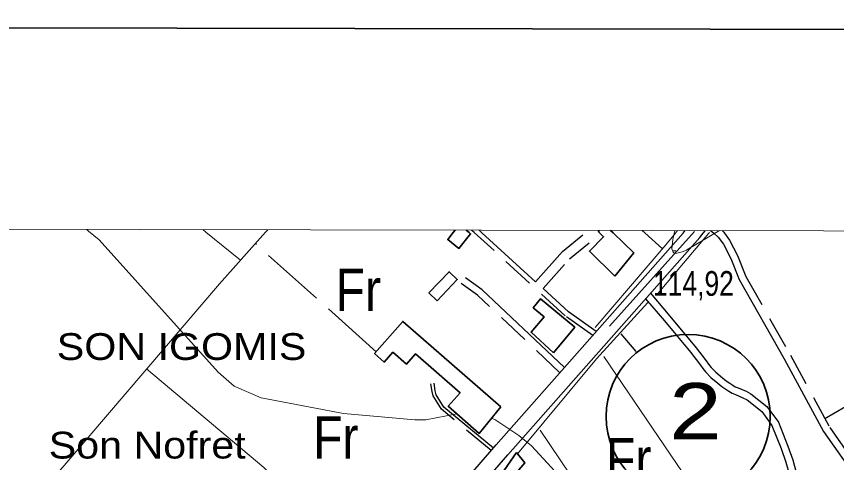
# Model space of a CAD drawing. Extents: x 483847 to 488453, y 4383581 to 4386795.
# Drawn here: x 486183.5 to 486474.2, y 4386361.3 to 4386519.6 of the extents above; entities that cross this region are included whole.
import ezdxf
from ezdxf.enums import TextEntityAlignment as Align

# ---------------------------------------------------------------- set-up
doc = ezdxf.new("R2010")
doc.units = 0
doc.header["$LTSCALE"] = 3.8
doc.linetypes.add('LONG_DASHED', pattern=[7.5, 6, -1.5])
doc.linetypes.add('MEDIUM_DASHED', pattern=[4.5, 3, -1.5])
for name, color, linetype, lineweight in [('1', 7, 'Continuous', 13), ('13', 7, 'Continuous', 25), ('25', 7, 'LONG_DASHED', 25), ('36', 7, 'Continuous', 25), ('38', 7, 'Continuous', 25), ('47', 7, 'Continuous', 35), ('51', 7, 'Continuous', 13), ('6', 7, 'Continuous', 35), ('7', 7, 'Continuous', 13), ('9', 7, 'Continuous', 13)]:
    doc.layers.add(name, color=color, linetype=linetype, lineweight=lineweight)
doc.layers.add('31', color=7, linetype='Continuous')
doc.layers.add('5', color=7, linetype='Continuous')

msp = doc.modelspace()

# ---------------------------------------------------------------- linework, layer by layer
at = {"layer": '1', "lineweight": 35}
msp.add_lwpolyline([(484035.03, 4386519.58), (487752.53, 4386512.52), (487747.86, 4384057.52), (484030.36, 4384064.59)], close=True, dxfattribs=at)
at = {"layer": '1'}
msp.add_lwpolyline([(484105.5, 4386448.1), (487681.9, 4386441.2), (487678, 4384129), (484100.5, 4384135.8)], close=True, dxfattribs=at)
at = {"layer": '25'}
msp.add_line((486311.07, 4386400.66), (486268.2, 4386438.96), dxfattribs=at)
msp.add_lwpolyline([(486470.05, 4386377.03), (486540.85, 4386417.71), (486530.1, 4386442.53)], dxfattribs=at)
at = {"layer": '36'}
for p, q in [((486419.82, 4386442.75), (486420.6, 4386443.63)), ((486426.98, 4386442.73), (486427.72, 4386443.62))]:
    msp.add_line(p, q, dxfattribs=at)
for points in [[(486304.43, 4386310.75), (486353.58, 4386367.64), (486419.82, 4386442.75)], [(486308, 4386306.63), (486357.67, 4386364.07), (486425.71, 4386441.21), (486426.98, 4386442.73)]]:
    msp.add_lwpolyline(points, dxfattribs=at)
at = {"layer": '38'}
for p, q in [((486348.51, 4386442.88), (486347.53, 4386443.77)), ((486367.53, 4386425.5), (486348.51, 4386442.88))]:
    msp.add_line(p, q, dxfattribs=at)
at = {"layer": '38', "linetype": 'MEDIUM_DASHED'}
for points in [[(486345.81, 4386442.89), (486344.99, 4386443.64), (486344.83, 4386443.78)], [(486387.8, 4386406.43), (486378.03, 4386413.43), (486345.81, 4386442.89)], [(486433.64, 4386443.61), (486434.21, 4386443.11), (486434.49, 4386442.72)], [(486434.49, 4386442.72), (486436.31, 4386440.2), (486439.11, 4386434.8), (486442.06, 4386427.36), (486457.9, 4386399.46), (486471.82, 4386373.74), (486486.78, 4386352.48), (486491.1, 4386348.94), (486494.66, 4386343.57), (486495.55, 4386341.07), (486495.52, 4386339.13)], [(486370.19, 4386423.06), (486379.57, 4386433.55), (486386.52, 4386439.29)], [(486376.16, 4386393.24), (486346.95, 4386420.72), (486341.2, 4386424.84)], [(486351.82, 4386365.61), (486334.16, 4386380.29), (486331.18, 4386384.98), (486330.82, 4386386.61), (486330.4, 4386389.32)]]:
    msp.add_lwpolyline(points, dxfattribs=at)
at = {"layer": '38'}
for points in [[(486429.54, 4386443.62), (486430.55, 4386442.86), (486430.71, 4386442.72)], [(486430.71, 4386442.72), (486432.29, 4386441.35), (486434.1, 4386438.84), (486436.75, 4386433.73), (486439.72, 4386426.24), (486455.63, 4386398.2), (486469.61, 4386372.37), (486484.87, 4386350.7), (486489.16, 4386347.19), (486492.33, 4386342.4), (486492.95, 4386340.64), (486492.93, 4386339.16)], [(486367.53, 4386425.5), (486377.07, 4386436.15), (486384.23, 4386442.07)], [(486377.83, 4386395.13), (486348.56, 4386422.67), (486342.67, 4386426.89)], [(486389, 4386407.79), (486379.18, 4386414.84), (486370.19, 4386423.06)], [(486408.24, 4386421.4), (486415.14, 4386413.31), (486424.51, 4386402.05), (486427.6, 4386397.88), (486429.22, 4386395.84), (486429.81, 4386395.09), (486431.43, 4386393.44), (486433.78, 4386391.45), (486435.03, 4386390.39), (486436.36, 4386389.56), (486437.4, 4386388.79), (486438.32, 4386388.27), (486439.36, 4386387.89), (486442.14, 4386386.64), (486443.88, 4386385.77), (486449.56, 4386381.3), (486453.58, 4386375.72), (486456.99, 4386367.23), (486458.73, 4386362.31), (486459.94, 4386357.8)], [(486406.53, 4386419.46), (486413.19, 4386411.65), (486422.5, 4386400.47), (486425.58, 4386396.33), (486427.21, 4386394.26), (486427.88, 4386393.4), (486429.68, 4386391.56), (486432.13, 4386389.5), (486433.51, 4386388.32), (486434.92, 4386387.44), (486436, 4386386.64), (486437.25, 4386385.94), (486438.39, 4386385.51), (486441.04, 4386384.32), (486442.5, 4386383.6), (486447.7, 4386379.52), (486451.31, 4386374.48), (486454.6, 4386366.32), (486456.28, 4386361.56), (486457.49, 4386357.04)], [(486352.57, 4386366.47), (486335.03, 4386381.06), (486332.25, 4386385.42), (486331.95, 4386386.82), (486331.54, 4386389.5)]]:
    msp.add_lwpolyline(points, dxfattribs=at)
at = {"layer": '47'}
for p, q in [((486339.06, 4386443.79), (486338.35, 4386442.9)), ((486344, 4386442.89), (486342.88, 4386443.78)), ((486394.13, 4386443.68), (486395.05, 4386442.79))]:
    msp.add_line(p, q, dxfattribs=at)
for points in [[(486338.35, 4386442.9), (486336.4, 4386440.44), (486340.33, 4386437.32), (486344.46, 4386442.53), (486344, 4386442.89)], [(486395.57, 4386427.52), (486386.62, 4386436.28), (486391.64, 4386441.42), (486390.22, 4386442.8)], [(486390.22, 4386442.8), (486389.73, 4386443.28), (486390.13, 4386443.69)], [(486395.05, 4386442.79), (486402.37, 4386435.71), (486395.57, 4386427.52)]]:
    msp.add_lwpolyline(points, dxfattribs=at)
for points in [[(486332.64, 4386418.75), (486339.77, 4386426.25), (486336.84, 4386429.04), (486329.71, 4386421.54)], [(486373.87, 4386400.22), (486381.43, 4386409.34), (486369.27, 4386419.41), (486366.68, 4386416.28), (486370.52, 4386413.09), (486365.92, 4386407.55)], [(486355.21, 4386381.13), (486320.45, 4386411.42), (486310.48, 4386399.99), (486313.89, 4386397.01), (486316.94, 4386400.51), (486321.78, 4386396.28), (486324.93, 4386399.9), (486340.75, 4386386.13), (486336.55, 4386381.32), (486347.55, 4386371.69)], [(486360.76, 4386364.92), (486354.09, 4386355.41), (486356.68, 4386352.97), (486363.71, 4386361.27)]]:
    msp.add_lwpolyline(points, close=True, dxfattribs=at)
at = {"layer": '51'}
for p, q in [((486249.54, 4386443.96), (486250.64, 4386443.07)), ((486250.64, 4386443.07), (486262.95, 4386433.11)), ((486271.85, 4386443.03), (486272.65, 4386443.92)), ((486405.29, 4386443.66), (486406.28, 4386442.77)), ((486406.28, 4386442.77), (486412.5, 4386437.16)), ((486428.99, 4386442.73), (486411.01, 4386421.45)), ((486417.15, 4386442.75), (486417.88, 4386443.64)), ((486429.18, 4386442.95), (486428.99, 4386442.73)), ((486456.75, 4386303.26), (486391.78, 4386398.99))]:
    msp.add_line(p, q, dxfattribs=at)
for points in [[(486195.55, 4386354.65), (486255.51, 4386424.8), (486271.85, 4386443.03)], [(486388.63, 4386409.24), (486413.66, 4386438.52), (486417.15, 4386442.75)], [(486407.29, 4386418.13), (486389.07, 4386398.2), (486361.13, 4386364.48)], [(486229.66, 4386394.55), (486271.24, 4386359.67), (486290.41, 4386340.8)], [(486428.28, 4386345.22), (486401.16, 4386325.39), (486369.2, 4386372.82)]]:
    msp.add_lwpolyline(points, dxfattribs=at)
at = {"layer": '6'}
msp.add_line((486393.79, 4386409.76), (486423.83, 4386443.25), dxfattribs=at)
at = {"layer": '6', "lineweight": 25}
msp.add_line((486397.72, 4386407.06), (486403.02, 4386400.72), dxfattribs=at)
at = {"layer": '6'}
msp.add_circle((486421.62, 4386377.7), 29.1, dxfattribs=at)
at = {"layer": '7'}
msp.add_line((486416.21, 4386436.45), (486417.21, 4386436.45), dxfattribs=at)
at = {"layer": '9'}
for points in [[(486208.43, 4386444.04), (486209.1, 4386443.4), (486212.88, 4386440.3), (486254.97, 4386393.43), (486260.66, 4386388.51), (486270.23, 4386384.26), (486299.48, 4386378.71), (486324.7, 4386376.52), (486328.59, 4386376.54), (486339.59, 4386378.65)], [(486432.77, 4386443.61), (486421.69, 4386437.19), (486421.19, 4386436.81), (486420.97, 4386436.69), (486419.48, 4386436.08), (486417.65, 4386435.56), (486416.94, 4386435.53), (486416.45, 4386435.83), (486416.32, 4386435.99), (486416.2, 4386436.18), (486415.81, 4386437.15), (486416.14, 4386440.45), (486416.91, 4386443.64)], [(486351.94, 4386377.1), (486353.05, 4386376.65), (486361.63, 4386370.93), (486366.07, 4386367.34), (486396.41, 4386334.35), (486400.31, 4386331.6), (486405.56, 4386332.26), (486446.97, 4386343.97), (486480.88, 4386347.97)]]:
    msp.add_lwpolyline(points, dxfattribs=at)

# ---------------------------------------------------------------- texts
at = {"layer": '13', "width": 1.25}
msp.add_text('2', height=20, dxfattribs=at).set_placement((486424.2, 4386369.57), align=Align.CENTER)
at = {"layer": '31', "width": 0.85}
for p in [(486304.69, 4386415.11), (486296.71, 4386362.78), (486400.55, 4386355.12)]:
    msp.add_text('Fr', height=15, dxfattribs=at).set_placement(p, align=Align.CENTER)
at = {"layer": '5', "width": 1.15}
for s, p in [('SON IGOMIS', (486286.28, 4386397.75)), ('Son Nofret', (486264.77, 4386362.79))]:
    msp.add_text(s, height=9.5, dxfattribs=at).set_placement(p, align=Align.RIGHT)
at = {"layer": '7', "width": 0.8}
msp.add_text('114,92', height=8.75, dxfattribs=at).set_placement((486409.18, 4386420.51))

doc.saveas('drawing.dxf')
